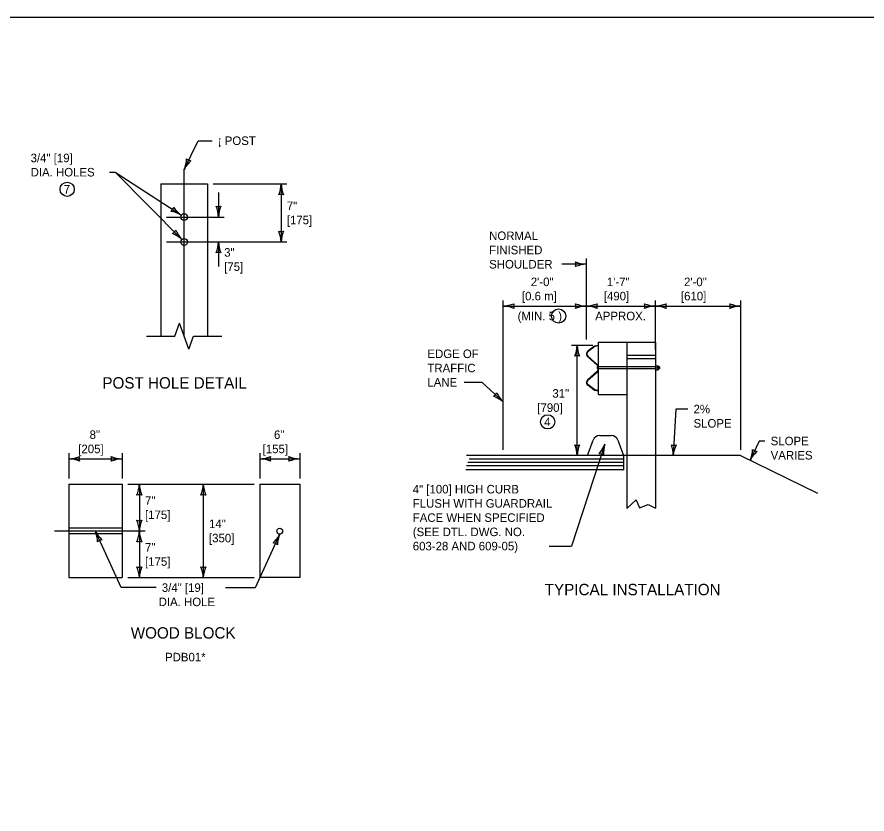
# Model space of a CAD drawing. Extents: x 49991.4 to 50021, y 49987.6 to 50011.4.
# Drawn here: x 50003.3 to 50009.28, y 49993.4 to 49999 of the extents above; entities that cross this region are included whole.
import ezdxf

# ---------------------------------------------------------------- set-up
doc = ezdxf.new("R2010")
doc.units = 0
for name, color, linetype in [('Level 1', 7, 'Continuous'), ('Level 2', 7, 'Continuous'), ('Level 3', 7, 'Continuous'), ('Level 4', 7, 'Continuous'), ('Level 5', 7, 'Continuous'), ('Level 6', 7, 'Continuous')]:
    doc.layers.add(name, color=color, linetype=linetype)

msp = doc.modelspace()

# ---------------------------------------------------------------- linework, layer by layer
at = {"layer": 'Level 1'}
for p, q in [((50004.3102, 49997.8268), (50004.6383, 49997.8268)), ((50004.3102, 49997.8268), (50004.3102, 49996.7559)), ((50004.6383, 49997.8268), (50004.6383, 49996.7559)), ((50007.36, 49996.6871), (50007.3121, 49996.6512)), ((50007.3613, 49996.6842), (50007.314, 49996.6487)), ((50007.3873, 49996.692), (50007.36, 49996.6871)), ((50007.3873, 49996.6887), (50007.3613, 49996.6842)), ((50007.3873, 49996.715), (50007.7874, 49996.715)), ((50007.3873, 49996.3478), (50007.3873, 49996.715)), ((50007.5862, 49996.715), (50007.5862, 49995.917)), ((50007.7874, 49996.715), (50007.7874, 49995.917)), ((50007.3107, 49996.6128), (50007.379, 49996.5533)), ((50007.3127, 49996.6152), (50007.3811, 49996.5556)), ((50007.3107, 49996.4502), (50007.3788, 49996.5096)), ((50007.3127, 49996.4479), (50007.3822, 49996.5084)), ((50007.3858, 49996.5338), (50007.378, 49996.5338)), ((50007.7874, 49996.5501), (50007.789, 49996.5501)), ((50007.7874, 49996.5172), (50007.789, 49996.5172)), ((50007.789, 49996.5501), (50007.789, 49996.5172)), ((50007.789, 49996.547), (50007.8063, 49996.547)), ((50007.789, 49996.5338), (50007.8063, 49996.5338)), ((50007.789, 49996.5206), (50007.8063, 49996.5206)), ((50007.8063, 49996.547), (50007.8063, 49996.5206)), ((50007.8167, 49996.5416), (50007.8063, 49996.5416)), ((50007.8167, 49996.526), (50007.8063, 49996.526)), ((50007.8167, 49996.5416), (50007.8167, 49996.526)), ((50007.36, 49996.3755), (50007.3121, 49996.4118)), ((50007.3613, 49996.3785), (50007.314, 49996.4143)), ((50007.3873, 49996.3707), (50007.36, 49996.3755)), ((50007.3873, 49996.3739), (50007.3613, 49996.3785)), ((50007.3873, 49996.3478), (50007.5862, 49996.3478)), ((50007.3098, 49995.917), (50007.3495, 49996.0262)), ((50007.3965, 49996.0591), (50007.4765, 49996.0591)), ((50007.5235, 49996.0262), (50007.5632, 49995.917)), ((50008.3868, 49995.917), (50006.4589, 49995.917)), ((50007.5657, 49995.8171), (50007.5657, 49995.917)), ((50008.3868, 49995.917), (50008.9261, 49995.654)), ((50007.5657, 49995.845), (50006.4599, 49995.845)), ((50007.5657, 49995.869), (50006.468, 49995.869)), ((50007.5657, 49995.893), (50006.4771, 49995.893)), ((50007.5657, 49995.8171), (50006.4553, 49995.8171)), ((50003.6622, 49995.7162), (50004.0371, 49995.7162)), ((50003.6622, 49995.7162), (50003.6622, 49995.0596)), ((50004.0371, 49995.7162), (50004.0371, 49995.0596)), ((50005.0051, 49995.7162), (50005.0051, 49995.0596)), ((50005.0051, 49995.7162), (50005.2864, 49995.7162)), ((50005.2864, 49995.7162), (50005.2864, 49995.0596)), ((50003.6622, 49995.0596), (50004.0371, 49995.0596)), ((50005.2864, 49995.0596), (50005.0051, 49995.0596))]:
    msp.add_line(p, q, dxfattribs=at)
msp.add_lwpolyline([(49999.3835, 49998.9992), (50016.7501, 49998.9992), (50016.7501, 49987.7988), (49999.3835, 49987.7988)], close=True, dxfattribs=at)
for centre, radius in [((50004.4742, 49997.5935), 0.0237), ((50004.4742, 49997.4185), 0.0237), ((50005.146, 49995.3869), 0.0205)]:
    msp.add_circle(centre, radius, dxfattribs=at)
for centre, radius, start, end in [((50007.3269, 49996.6314), 0.0247, 126.89692, 228.93931), ((50007.3269, 49996.6314), 0.0216, 126.89692, 228.93931), ((50007.3629, 49996.5283), 0.0246, 310.4718, 353.52997), ((50007.3629, 49996.5347), 0.0246, 6.47003, 48.93931), ((50007.3629, 49996.5347), 0.0277, 28.21928, 48.93931), ((50007.3629, 49996.5283), 0.0277, 314.1015, 331.78072), ((50007.3269, 49996.4316), 0.0247, 131.06069, 233.10308), ((50007.3269, 49996.4316), 0.0216, 131.06069, 233.10308), ((50007.3965, 49996.0091), 0.05, 90, 159.99404), ((50007.4765, 49996.0091), 0.05, 20.00596, 90)]:
    msp.add_arc(centre, radius, start, end, dxfattribs=at)
for centre, major_axis, ratio, start_param, end_param in [((50007.3858, 49996.5336), (0, 0.0118), 0.663267, 0.091019, 3.253139), ((50007.7995, 49996.5404), (-0.00663, -0.00083), 0.990733, 1.458806, 4.470369), ((50007.7995, 49996.5272), (-0.00663, -0.00083), 0.990733, 1.560943, 4.574691)]:
    msp.add_ellipse(centre, major_axis=major_axis, ratio=ratio, start_param=start_param, end_param=end_param, dxfattribs=at)
at = {"layer": 'Level 2'}
for centre in [(50003.6512, 49997.7888), (50007.107, 49996.8976), (50007.0297, 49996.1545)]:
    msp.add_circle(centre, 0.05, dxfattribs=at)
at = {"layer": 'Level 3'}
for p, q in [((50004.4742, 49997.9268), (50004.572, 49998.13)), ((50004.572, 49998.13), (50004.6703, 49998.13)), ((50003.9479, 49997.9088), (50003.9879, 49997.9088)), ((50003.9879, 49997.9088), (50004.4575, 49997.4353)), ((50003.9879, 49997.9088), (50004.4543, 49997.6064)), ((50004.6783, 49997.8268), (50005.1957, 49997.8268)), ((50005.1557, 49997.8268), (50005.1557, 49997.4185)), ((50004.7155, 49997.767), (50004.7155, 49997.5935)), ((50004.7155, 49997.4185), (50004.7155, 49997.245)), ((50007.3022, 49996.732), (50007.3022, 49997.302)), ((50007.3022, 49997.262), (50007.1288, 49997.262)), ((50006.7169, 49995.957), (50006.7169, 49997.0081)), ((50007.7874, 49996.6616), (50007.7874, 49997.0081)), ((50008.3868, 49997.0081), (50008.3868, 49995.957)), ((50006.7169, 49996.9681), (50007.3022, 49996.9681)), ((50007.3022, 49996.9681), (50007.7874, 49996.9681)), ((50007.7874, 49996.9681), (50008.3868, 49996.9681)), ((50007.3473, 49996.692), (50007.1975, 49996.692)), ((50007.2375, 49995.917), (50007.2375, 49996.692)), ((50006.4421, 49996.4326), (50006.5675, 49996.4326)), ((50006.5675, 49996.4326), (50006.7169, 49996.2948)), ((50007.9308, 49996.2442), (50007.9125, 49995.917)), ((50008.0155, 49996.2442), (50007.9308, 49996.2442)), ((50007.4307, 49995.9974), (50007.1982, 49995.2814)), ((50008.5179, 49996.0199), (50008.4542, 49995.8841)), ((50008.5579, 49996.0199), (50008.5179, 49996.0199)), ((50003.6622, 49995.9342), (50003.6622, 49995.7562)), ((50004.0371, 49995.9342), (50004.0371, 49995.7562)), ((50005.0051, 49995.9342), (50005.0051, 49995.7562)), ((50005.2866, 49995.9342), (50005.2866, 49995.7562)), ((50003.6622, 49995.8942), (50004.0371, 49995.8942)), ((50005.0051, 49995.8942), (50005.2866, 49995.8942)), ((50004.0771, 49995.7162), (50004.9651, 49995.7162)), ((50004.1589, 49995.7162), (50004.1589, 49995.3866)), ((50004.6087, 49995.7162), (50004.6087, 49995.0596)), ((50004.0302, 49994.9896), (50003.8496, 49995.3866)), ((50004.1589, 49995.3866), (50004.1589, 49995.0596)), ((50004.9747, 49994.9896), (50005.146, 49995.3663)), ((50007.0401, 49995.2814), (50007.1982, 49995.2814)), ((50004.0771, 49995.0596), (50004.9651, 49995.0596)), ((50004.2768, 49994.9896), (50004.0302, 49994.9896)), ((50004.7654, 49994.9896), (50004.9747, 49994.9896))]:
    msp.add_line(p, q, dxfattribs=at)
for centre, radius, start, end in [((50004.2585, 49998.0147), 0.233, 337.82731, 357.07716), ((50004.5284, 49998.043), 0.0548, 227.13882, 262.86118), ((50004.6717, 49997.8246), 0.2223, 132.45601, 152.63952), ((50004.9336, 49997.836), 0.2223, 337.45601, 357.63952), ((50005.3885, 49997.8383), 0.233, 182.82731, 202.07716), ((50005.1557, 49997.6986), 0.0548, 72.13882, 107.86118), ((50004.3468, 49997.6761), 0.0548, 309.18565, 344.90801), ((50004.5829, 49997.7878), 0.2223, 214.50284, 234.68635), ((50004.7155, 49997.7217), 0.0548, 252.13882, 287.86118), ((50004.4828, 49997.582), 0.233, 2.82731, 22.07716), ((50004.9376, 49997.5844), 0.2223, 157.45601, 177.63952), ((50004.3374, 49997.4049), 0.233, 59.87414, 79.12399), ((50004.3673, 49997.5263), 0.0548, 296.90501, 332.62737), ((50004.3004, 49997.2633), 0.233, 47.5935, 66.84335), ((50004.6217, 49997.5852), 0.2223, 202.2222, 222.40571), ((50005.1557, 49997.5467), 0.0548, 252.13882, 287.86118), ((50004.923, 49997.407), 0.233, 2.82731, 22.07716), ((50005.3779, 49997.4093), 0.2223, 157.45601, 177.63952), ((50004.4934, 49997.4276), 0.2223, 337.45601, 357.63952), ((50004.9482, 49997.43), 0.233, 182.82731, 202.07716), ((50004.7155, 49997.2903), 0.0548, 72.13882, 107.86118), ((50007.174, 49997.262), 0.0548, 342.13882, 17.86118), ((50007.3137, 49997.4947), 0.233, 247.92284, 267.17269), ((50007.3114, 49997.0399), 0.2223, 92.36048, 112.54399), ((50006.7054, 49997.2008), 0.233, 272.82731, 292.07716), ((50006.8451, 49996.9681), 0.0548, 162.13882, 197.86118), ((50007.3114, 49997.1902), 0.2223, 247.45601, 267.63952), ((50007.174, 49996.9681), 0.0548, 342.13882, 17.86118), ((50007.2907, 49997.2008), 0.233, 272.82731, 292.07716), ((50007.4304, 49996.9681), 0.0548, 162.13882, 197.86118), ((50007.7966, 49997.1902), 0.2223, 247.45601, 267.63952), ((50007.6592, 49996.9681), 0.0548, 342.13882, 17.86118), ((50007.7759, 49997.2008), 0.233, 272.82731, 292.07716), ((50007.9156, 49996.9681), 0.0548, 162.13882, 197.86118), ((50008.396, 49997.1902), 0.2223, 247.45601, 267.63952), ((50008.2586, 49996.9681), 0.0548, 342.13882, 17.86118), ((50006.7078, 49996.746), 0.2223, 67.45601, 87.63952), ((50007.3137, 49996.7354), 0.233, 92.82731, 112.07716), ((50007.2931, 49996.746), 0.2223, 67.45601, 87.63952), ((50007.7989, 49996.7354), 0.233, 92.82731, 112.07716), ((50007.7783, 49996.746), 0.2223, 67.45601, 87.63952), ((50008.3983, 49996.7354), 0.233, 92.82731, 112.07716), ((50007.0154, 49996.7012), 0.2223, 337.45601, 357.63952), ((50007.4702, 49996.7035), 0.233, 182.82731, 202.07716), ((50007.2375, 49996.5638), 0.0548, 72.13882, 107.86118), ((50006.6227, 49996.3817), 0.0548, 299.45174, 335.1741), ((50006.5676, 49996.1159), 0.233, 50.14023, 69.39008), ((50006.8742, 49996.4519), 0.2223, 204.76893, 224.95244), ((50007.2375, 49996.0452), 0.0548, 252.13882, 287.86118), ((50007.0048, 49995.9055), 0.233, 2.82731, 22.07716), ((50007.4596, 49995.9078), 0.2223, 157.45601, 177.63952), ((50007.2223, 49996.0747), 0.2223, 319.46868, 339.65218), ((50007.6556, 49995.9365), 0.233, 164.83998, 184.08983), ((50007.9196, 49996.045), 0.0548, 248.92688, 284.64924), ((50007.6795, 49995.9186), 0.233, 359.61537, 18.86522), ((50008.1337, 49995.8954), 0.2223, 154.24407, 174.42758), ((50003.6507, 49996.1269), 0.233, 272.82731, 292.07716), ((50003.7904, 49995.8942), 0.0548, 162.13882, 197.86118), ((50004.0462, 49996.1163), 0.2223, 247.45601, 267.63952), ((50003.9089, 49995.8942), 0.0548, 342.13882, 17.86118), ((50004.9936, 49996.1269), 0.233, 272.82731, 292.07716), ((50005.1333, 49995.8942), 0.0548, 162.13882, 197.86118), ((50005.2957, 49996.1163), 0.2223, 247.45601, 267.63952), ((50005.1584, 49995.8942), 0.0548, 342.13882, 17.86118), ((50007.3911, 49995.8755), 0.0548, 54.15148, 89.87385), ((50008.2386, 49995.9726), 0.233, 337.68312, 356.93297), ((50008.6514, 49995.7815), 0.2223, 132.31182, 152.49532), ((50008.5087, 49996.0002), 0.0548, 226.99462, 262.71699), ((50003.653, 49995.6721), 0.2223, 67.45601, 87.63952), ((50004.0486, 49995.6615), 0.233, 92.82731, 112.07716), ((50004.9959, 49995.6721), 0.2223, 67.45601, 87.63952), ((50005.2981, 49995.6615), 0.233, 92.82731, 112.07716), ((50003.9367, 49995.7254), 0.2223, 337.45601, 357.63952), ((50004.3916, 49995.7277), 0.233, 182.82731, 202.07716), ((50004.3865, 49995.7254), 0.2223, 337.45601, 357.63952), ((50004.8414, 49995.7277), 0.233, 182.82731, 202.07716), ((50004.1589, 49995.588), 0.0548, 72.13882, 107.86118), ((50004.6087, 49995.588), 0.0548, 72.13882, 107.86118), ((50004.1589, 49995.5148), 0.0548, 252.13882, 287.86118), ((50003.9262, 49995.3751), 0.233, 2.82731, 22.07716), ((50004.381, 49995.3775), 0.2223, 157.45601, 177.63952), ((50003.6436, 49995.303), 0.2223, 1.91578, 22.09929), ((50004.0566, 49995.4934), 0.233, 207.28708, 226.53693), ((50003.9367, 49995.3958), 0.2223, 337.45601, 357.63952), ((50004.3916, 49995.3981), 0.233, 182.82731, 202.07716), ((50003.9027, 49995.2699), 0.0548, 96.59859, 132.32095), ((50004.1589, 49995.2584), 0.0548, 72.13882, 107.86118), ((50004.9389, 49995.4732), 0.233, 313.46307, 332.71292), ((50005.352, 49995.2827), 0.2223, 157.90071, 178.08422), ((50005.0929, 49995.2496), 0.0548, 47.67905, 83.40141), ((50004.1589, 49995.1878), 0.0548, 252.13882, 287.86118), ((50003.9262, 49995.0481), 0.233, 2.82731, 22.07716), ((50004.381, 49995.0505), 0.2223, 157.45601, 177.63952), ((50004.6087, 49995.1878), 0.0548, 252.13882, 287.86118), ((50004.376, 49995.0481), 0.233, 2.82731, 22.07716), ((50004.8308, 49995.0505), 0.2223, 157.45601, 177.63952)]:
    msp.add_arc(centre, radius, start, end, dxfattribs=at)
at = {"layer": 'Level 4'}
for p, q in [((50007.7874, 49996.6209), (50007.5862, 49996.6209)), ((50007.7874, 49996.5964), (50007.5862, 49996.5964)), ((50007.7874, 49996.5416), (50007.3873, 49996.5416)), ((50007.7874, 49996.526), (50007.3873, 49996.526)), ((50007.5862, 49995.917), (50007.5862, 49995.5462)), ((50007.7874, 49995.917), (50007.7874, 49995.5473)), ((50007.5862, 49995.5462), (50007.6523, 49995.6061)), ((50007.6523, 49995.6061), (50007.6767, 49995.5502)), ((50007.6767, 49995.5502), (50007.7362, 49995.5747)), ((50007.7362, 49995.5747), (50007.7874, 49995.5473)), ((50004.0371, 49995.4083), (50003.6622, 49995.4083)), ((50004.0371, 49995.3674), (50003.6622, 49995.3674))]:
    msp.add_line(p, q, dxfattribs=at)
at = {"layer": 'Level 5'}
for p, q in [((50004.4742, 49996.756), (50004.4742, 49997.9268)), ((50004.3505, 49997.5935), (50004.7555, 49997.5935)), ((50004.3505, 49997.4185), (50005.1957, 49997.4185)), ((50004.1989, 49995.3866), (50003.5622, 49995.3866))]:
    msp.add_line(p, q, dxfattribs=at)
at = {"layer": 'Level 6'}
for p, q in [((50004.4095, 49996.7559), (50004.4419, 49996.8473)), ((50004.4743, 49996.7559), (50004.4419, 49996.8473)), ((50004.2102, 49996.7559), (50004.4095, 49996.7559)), ((50004.5067, 49996.6645), (50004.4743, 49996.7559)), ((50004.5067, 49996.6645), (50004.5391, 49996.7559)), ((50004.5391, 49996.7559), (50004.7383, 49996.7559))]:
    msp.add_line(p, q, dxfattribs=at)

# ---------------------------------------------------------------- texts
at = {"layer": 'Level 2'}
for s, height, p in [('¡ POST', 0.06, (50004.7103, 49998.1)), ('3/4" [19]', 0.06, (50003.3945, 49997.9788)), ('DIA. HOLES', 0.06, (50003.3945, 49997.8788)), ('7', 0.06, (50003.6274, 49997.7588)), ('7"', 0.06, (50005.1957, 49997.6426)), ('[175]', 0.06, (50005.1957, 49997.5426)), ('NORMAL', 0.06, (50006.6185, 49997.432)), ('3"', 0.06, (50004.7555, 49997.315)), ('FINISHED', 0.06, (50006.6185, 49997.332)), ('SHOULDER', 0.06, (50006.6185, 49997.232)), ('[75]', 0.06, (50004.7555, 49997.215)), ('2\'-0"', 0.06, (50006.9111, 49997.1081)), ('1\'-7"', 0.06, (50007.4463, 49997.1081)), ('2\'-0"', 0.06, (50007.9886, 49997.1081)), ('[0.6 m]', 0.06, (50006.8489, 49997.0081)), ('[490]', 0.06, (50007.4246, 49997.0081)), ('[610]', 0.06, (50007.9669, 49997.0081)), ('(MIN. 5 )', 0.06, (50006.8186, 49996.8681)), ('APPROX.', 0.06, (50007.3641, 49996.8681)), ('EDGE OF', 0.06, (50006.1842, 49996.6026)), ('TRAFFIC', 0.06, (50006.1842, 49996.5026)), ('POST HOLE DETAIL', 0.08, (50003.899, 49996.3883)), ('LANE', 0.06, (50006.1842, 49996.4026)), ('31"', 0.06, (50007.0629, 49996.3245)), ('[790]', 0.06, (50006.9571, 49996.2245)), ('2% ', 0.06, (50008.0555, 49996.2142)), ('4', 0.06, (50007.0057, 49996.1245)), ('SLOPE', 0.06, (50008.0555, 49996.1142)), ('8"', 0.06, (50003.8093, 49996.0342)), ('6"', 0.06, (50005.1055, 49996.0342)), ('SLOPE', 0.06, (50008.5979, 49995.9899)), ('[205]', 0.06, (50003.7294, 49995.9342)), ('[155]', 0.06, (50005.0256, 49995.9342)), ('VARIES', 0.06, (50008.5979, 49995.8899)), ('4" [100] HIGH CURB', 0.06, (50006.0814, 49995.6514)), ('7"', 0.06, (50004.1989, 49995.5714)), ('FLUSH WITH GUARDRAIL', 0.06, (50006.0814, 49995.5514)), ('[175]', 0.06, (50004.1989, 49995.4714)), ('FACE WHEN SPECIFIED', 0.06, (50006.0814, 49995.4514)), ('14"', 0.06, (50004.6487, 49995.4079)), ('[350]', 0.06, (50004.6487, 49995.3079)), ('(SEE DTL. DWG. NO.', 0.06, (50006.0814, 49995.3514)), ('603-28 AND 609-05)', 0.06, (50006.0814, 49995.2514)), ('7"', 0.06, (50004.1989, 49995.2431)), ('[175]', 0.06, (50004.1989, 49995.1431)), ('3/4" [19]', 0.06, (50004.3168, 49994.9596)), ('TYPICAL INSTALLATION', 0.08, (50007.0092, 49994.9362)), ('DIA. HOLE', 0.06, (50004.2947, 49994.8596)), ('WOOD BLOCK', 0.08, (50004.0985, 49994.6315)), ('PDB01*', 0.06, (50004.3396, 49994.4715))]:
    msp.add_text(s, height=height, dxfattribs=at).set_placement(p)

doc.saveas('drawing.dxf')
